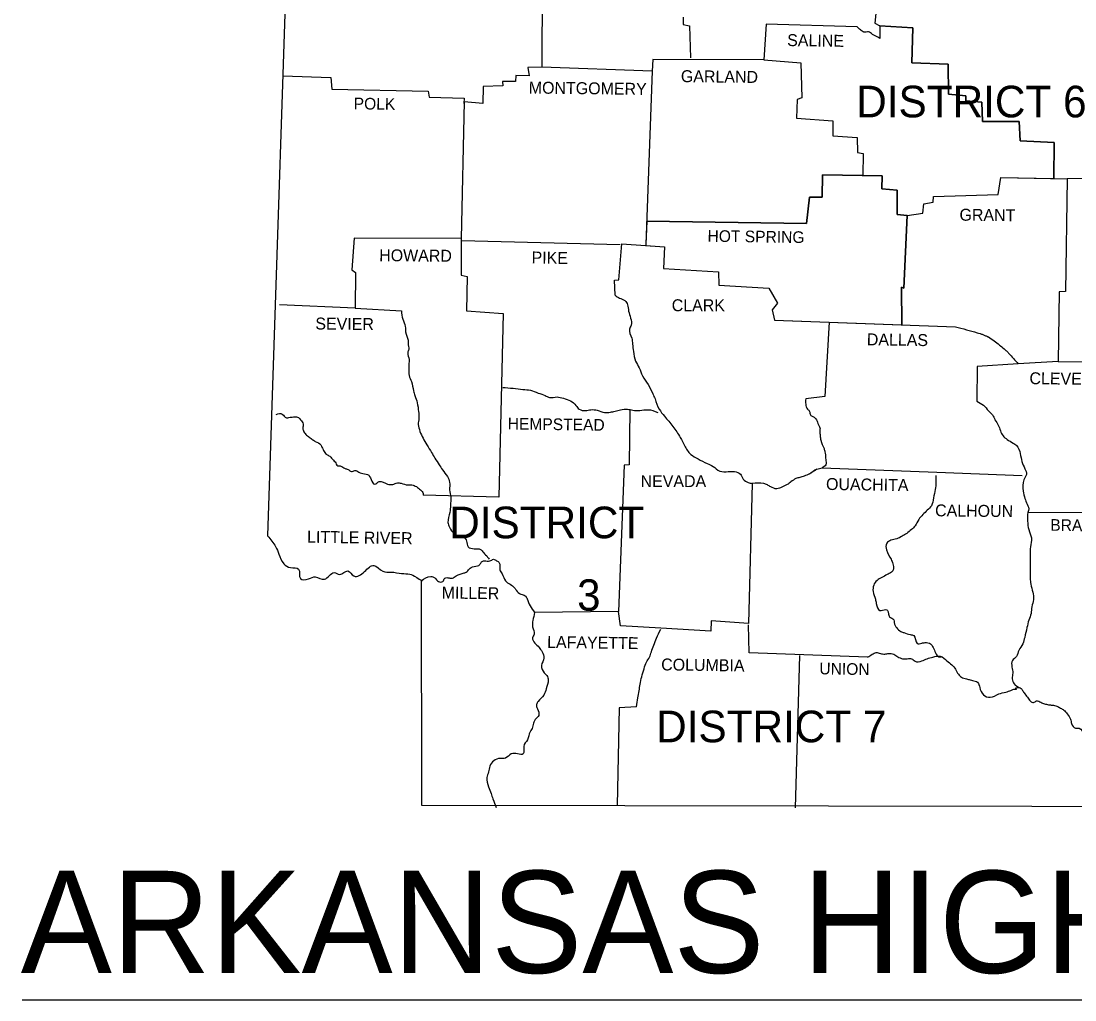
# Model space of a CAD drawing. Extents: x -984 to 3998, y 83 to 2143.
# Drawn here: x 2628.2 to 2999.8, y 1332.5 to 1677.5 of the extents above; entities that cross this region are included whole.
import ezdxf

# ---------------------------------------------------------------- set-up
doc = ezdxf.new("R2010")
doc.units = 0
for name, color, linetype in [('Level 1', 7, 'Continuous'), ('Level 2', 7, 'Continuous'), ('Level 3', 7, 'Continuous'), ('Level 45', 7, 'Continuous')]:
    doc.layers.add(name, color=color, linetype=linetype)

msp = doc.modelspace()

# ---------------------------------------------------------------- linework, layer by layer
at = {"layer": 'Level 1'}
for points in [[(2703.71, 1924.06), (2723.96, 1761.45), (2715.15, 1496.01)], [(2812.02, 1718.5), (2811.82, 1661.26), (2806.93, 1661.16), (2807.32, 1658.23), (2802.62, 1658.32), (2802.53, 1656.17), (2797.93, 1656.17), (2798.03, 1654.61), (2791.18, 1654.41), (2791.08, 1648.44), (2784.43, 1649.03), (2783.35, 1600.89), (2745.68, 1600.99), (2744.8, 1589.84), (2746.17, 1588.86), (2746.07, 1576.33), (2719.36, 1577.51)], [(2961.91, 1690.42), (2954.86, 1691.2), (2955.16, 1688.56), (2942.34, 1688.07), (2941.95, 1684.25), (2929.91, 1683.57), (2929.23, 1676.72), (2930.99, 1675.84), (2930.99, 1671.34)], [(2922.97, 1675.45), (2890.97, 1676.42), (2890.09, 1663.8), (2850.96, 1664), (2850.76, 1659.79)], [(2861.72, 1678.87), (2861.62, 1676.23), (2863.87, 1675.84), (2864.26, 1664.49)], [(2930.99, 1675.78), (2942.63, 1675.05), (2942.24, 1662.82), (2955.06, 1662.34), (2955.26, 1651.67), (2961.32, 1651.18), (2961.32, 1649.32), (2967, 1648.93), (2967.19, 1642.08), (2980.11, 1642.08), (2980.5, 1635.33), (2992.44, 1634.74), (2992.34, 1622.01)], [(2850.76, 1659.79), (2811.82, 1661.26)], [(2890.09, 1663.8), (2903.11, 1662.73), (2903.5, 1650.4), (2901.83, 1649.81), (2901.64, 1643.26), (2914.46, 1642.38), (2914.46, 1636.99), (2922.97, 1636.51), (2923.07, 1631.12), (2925.12, 1630.83), (2925.02, 1623.1)], [(2720.54, 1658.23), (2737.46, 1657.64), (2737.85, 1653.53), (2771.71, 1652.84), (2772.1, 1650.69), (2784.43, 1650.3), (2784.33, 1648.44)], [(2850.76, 1659.79), (2848.51, 1598.84)], [(3109.06, 1633.28), (3072.08, 1634.26), (3071.88, 1622.22), (2997.03, 1621.93)], [(2848.81, 1606.96), (2905.16, 1606.17), (2906.24, 1615.47), (2910.64, 1615.47), (2910.74, 1623.3), (2931.87, 1623), (2931.68, 1618.31), (2937.16, 1617.92), (2937.16, 1609.31), (2940.68, 1609.01)], [(2940.68, 1609.01), (2946.16, 1609.79), (2946.55, 1613.12), (2949.78, 1613.71), (2949.97, 1615.67), (2972.77, 1616.35), (2973.65, 1622.32), (2997.03, 1621.93)], [(2997.04, 1621.93), (2996.45, 1582.2), (2994.2, 1582.11), (2993.9, 1557.55)], [(2940.68, 1609.01), (2939.5, 1583.38), (2938.62, 1583.67), (2938.72, 1570.48)], [(2783.35, 1600.89), (2783.35, 1587.88), (2785.5, 1587.49), (2785.31, 1575.35), (2798.22, 1574.38), (2796.66, 1509.7), (2770.04, 1510.39)], [(2783.55, 1600.21), (2839.51, 1598.74)], [(2837.65, 1580.83), (2837.46, 1586.22), (2839.02, 1586.31), (2840, 1598.93), (2855.07, 1597.96), (2854.68, 1590.23), (2874.15, 1589.15), (2874.24, 1584.45), (2891.85, 1583.38), (2894.89, 1578.09), (2893.03, 1575.75), (2893.91, 1572.13), (2957.7, 1569.78)], [(2746.07, 1576.33), (2762.31, 1575.35)], [(2913.15, 1571.42), (2911.62, 1545.12), (2904.87, 1544.34)], [(2993.9, 1557.55), (2979.78, 1556.68)], [(2993.9, 1557.55), (3028.54, 1557.35)], [(2979.78, 1556.68), (2965.33, 1555.79), (2965.24, 1543.56)], [(2842.84, 1540.62), (2842.64, 1521.15), (2840.88, 1520.96), (2838.92, 1469.39)], [(2910.64, 1519.98), (2951.15, 1518.51), (2981.18, 1517.34)], [(2885.98, 1514.5), (2884.71, 1465.19), (2871.5, 1466.07), (2871.41, 1462.45), (2853.79, 1463.52)], [(2983.14, 1504.32), (3027.36, 1504.42)], [(2769.26, 1480.25), (2769.46, 1401.1), (3128.04, 1400.51)], [(2853.79, 1463.52), (2839.61, 1464.31), (2838.92, 1469.39), (2809.28, 1469.1)], [(2926.69, 1453.25), (2884.91, 1454.82), (2884.71, 1464.7)], [(2902.72, 1453.93), (2901.15, 1400.22)], [(2845.18, 1435.83), (2839.12, 1435.44), (2838.43, 1401)]]:
    msp.add_lwpolyline(points, dxfattribs=at)
for points in [[(2930.99, 1671.34), (2930.31, 1671.83), (2928.45, 1672.8), (2926.98, 1673.68), (2925.41, 1673.59), (2924.14, 1674.37), (2922.97, 1675.45)], [(2837.65, 1580.83), (2839.22, 1579.86), (2841.08, 1578.98), (2842.05, 1577.51), (2842.45, 1575.26), (2843.13, 1572.81), (2843.33, 1570.27), (2842.74, 1568.9), (2843.52, 1565.77), (2843.82, 1563.61), (2844.11, 1561.07), (2844.89, 1557.65), (2846.16, 1555.3), (2847.34, 1552.46), (2849.29, 1549.43), (2850.96, 1546.1), (2851.74, 1544.34), (2853.21, 1540.72), (2855.07, 1538.27), (2858, 1534.56), (2860.64, 1530.74), (2862.11, 1527.9), (2864.36, 1524.77), (2866.91, 1523.21), (2870.13, 1521.54), (2872.19, 1520.56), (2874.54, 1518.9), (2877.57, 1518.71), (2879.82, 1518.71), (2881.88, 1517.82), (2882.85, 1516.06), (2884.61, 1514.89), (2885.98, 1514.5)], [(2762.31, 1575.35), (2762.8, 1572.42), (2763.68, 1569.88), (2763.78, 1567.92), (2764.66, 1564.98), (2764.66, 1563.91), (2764.96, 1561.76), (2764.56, 1560.58), (2765.05, 1558.23), (2764.96, 1556.47), (2764.96, 1555), (2765.05, 1552.56), (2765.84, 1550.41), (2766.62, 1547.18), (2767.11, 1545.51), (2767.89, 1542.97), (2768.38, 1539.84), (2768.48, 1537.49), (2768.28, 1535.34), (2768.87, 1532.89), (2769.95, 1530.45), (2771.32, 1528.1), (2772.98, 1525.46), (2774.15, 1523.4), (2775.62, 1521.15), (2776.79, 1519.29), (2778.56, 1516.94), (2779.34, 1514.99), (2779.34, 1512.25), (2779.73, 1509.7), (2779.63, 1506.87), (2779.44, 1504.32), (2778.75, 1500.8), (2779.24, 1499.14), (2781.1, 1496.69), (2782.27, 1496.01), (2784.33, 1495.61), (2785.31, 1494.24), (2785.89, 1492.19), (2787.95, 1491.51), (2790.2, 1491.31), (2791.27, 1490.14), (2792.74, 1488.57), (2793.23, 1487.79)], [(2957.7, 1569.78), (2965.33, 1567.63), (2966.33, 1567.33), (2967.32, 1567), (2968.3, 1566.61), (2968.77, 1566.4), (2969.01, 1566.28), (2969.25, 1566.16), (2971.28, 1564.84), (2973.16, 1563.32), (2974.83, 1561.96), (2975.64, 1561.25), (2976.39, 1560.48), (2979.78, 1556.68)], [(2798.03, 1548.35), (2801.74, 1548.06), (2805.17, 1547.67), (2807.81, 1547.37), (2810.55, 1546.39), (2813, 1545.51), (2814.56, 1544.83), (2817.2, 1545.02), (2819.45, 1544.54), (2822, 1543.65), (2823.86, 1541.99), (2825.03, 1540.72), (2827.28, 1540.23), (2829.14, 1540.52), (2831.39, 1540.33), (2833.93, 1539.55), (2835.99, 1539.64), (2837.65, 1540.03), (2839.61, 1540.52), (2842.05, 1540.72), (2843.91, 1540.33), (2846.36, 1540.23), (2849.2, 1540.52), (2852.72, 1539.55)], [(2904.87, 1544.34), (2904.87, 1542.48), (2905.55, 1540.72), (2906.24, 1539.94), (2906.53, 1538.66), (2907.41, 1538.08), (2908.68, 1536.9), (2909.37, 1535.24), (2909.86, 1534.16), (2909.86, 1532.79), (2909.96, 1531.42), (2910.15, 1529.76), (2911.33, 1526.83), (2911.62, 1525.65), (2911.81, 1524.67), (2911.91, 1523.01), (2911.91, 1521.05), (2910.64, 1519.98)], [(2965.24, 1543.56), (2967.49, 1542.09), (2969.34, 1540.13), (2970.71, 1538.66), (2971.59, 1537), (2972.77, 1535.04), (2974.43, 1531.33), (2975.9, 1530.05), (2977.95, 1528.78), (2979.23, 1527.9), (2980.5, 1525.06), (2981.09, 1522.23), (2982.16, 1519.68), (2982.65, 1517.73), (2981.77, 1515.77), (2981.57, 1511.86), (2982.16, 1509.21), (2982.94, 1507.26), (2983.43, 1505.01), (2983.14, 1504.32)], [(2718.19, 1538.86), (2720.34, 1538.96), (2721.81, 1537.69), (2722.69, 1537.78), (2724.25, 1537.98), (2725.72, 1537.88), (2726.8, 1537), (2727.68, 1535.44), (2727.58, 1533.97), (2727.68, 1533.38), (2728.36, 1532.11), (2729.54, 1531.13), (2730.81, 1530.15), (2731.98, 1529.37), (2733.94, 1528.1), (2734.14, 1527.71), (2734.92, 1526.14), (2735.9, 1524.87), (2737.07, 1524.09), (2738.34, 1522.72), (2738.93, 1522.13), (2739.91, 1520.76), (2740.98, 1520.66), (2742.45, 1519.78), (2743.53, 1519.49), (2744.7, 1518.71), (2745.88, 1519.1), (2747.34, 1518.51), (2749.3, 1517.92), (2750.38, 1517.73), (2751.65, 1515.87), (2752.92, 1514.3), (2754.49, 1515.18), (2757.42, 1514.3), (2759.28, 1514.2), (2760.94, 1514.69), (2762.22, 1514.6), (2764.56, 1514.01), (2766.03, 1514.01), (2767.6, 1513.42), (2769.06, 1512.25), (2770.04, 1510.98), (2770.04, 1510.39)], [(2908.78, 1519.59), (2906.24, 1517.92), (2904.28, 1517.14), (2902.81, 1516.65), (2901.44, 1516.26), (2899.68, 1515.09), (2898.31, 1514.11), (2896.45, 1513.23), (2894.69, 1512.64), (2892.54, 1513.32), (2891.37, 1514.01), (2890.09, 1514.5), (2885.98, 1514.5)], [(2906.24, 1517.92), (2908.78, 1519.59), (2910.64, 1519.98)], [(2950.75, 1517.34), (2950.56, 1512.44), (2949.87, 1509.41), (2949.19, 1506.67), (2947.72, 1505.11), (2946.16, 1503.54), (2944.69, 1501.78), (2943.42, 1499.63), (2942.14, 1498.26), (2940.48, 1496.89), (2938.82, 1495.91), (2936.96, 1495.03), (2934.9, 1494.54), (2933.44, 1493.46), (2933.34, 1491.11), (2935, 1487.79), (2935.59, 1486.22), (2935.79, 1484.36), (2935.1, 1483.29), (2933.53, 1482.41), (2931.68, 1481.33), (2930.01, 1480.35), (2928.84, 1478.69), (2928.64, 1476.44), (2929.43, 1473.8), (2929.72, 1472.23), (2930.99, 1469.78), (2931.97, 1469.88), (2933.73, 1469.78), (2933.93, 1469.3), (2934.02, 1468.81), (2934.42, 1467.53), (2935.88, 1466.46), (2936.08, 1465.48), (2936.96, 1463.62), (2938.43, 1462.35), (2939.5, 1461.96), (2941.75, 1461.27), (2942.93, 1460.98), (2944.2, 1458.14), (2945.77, 1458.24), (2946.94, 1458.44), (2948.9, 1457.95), (2949.78, 1456.77), (2950.66, 1454.82), (2951.83, 1453.45), (2952.61, 1453.45)], [(2983.14, 1504.32), (2983.53, 1498.26), (2984.41, 1495.32), (2984.12, 1492.19), (2984.02, 1489.16), (2984.02, 1486.42), (2984.02, 1483.78), (2984.02, 1481.04), (2984.22, 1479.08), (2984.9, 1476.24), (2985.19, 1473.6), (2984.61, 1471.06), (2984.31, 1468.71), (2983.53, 1466.36), (2982.85, 1463.72), (2982.06, 1460.29), (2981.38, 1458.04), (2980.01, 1455.7), (2979.13, 1453.54), (2977.76, 1452.17), (2977.56, 1449.83), (2977.86, 1447.67), (2977.66, 1445.72), (2978.35, 1443.86), (2980.11, 1442.59)], [(2715.15, 1496.01), (2717.99, 1492.29), (2719.17, 1489.65), (2720.83, 1486.22), (2723.28, 1484.85), (2726.11, 1484.36), (2726.7, 1481.04), (2729.63, 1480.94), (2731.98, 1481.62), (2735.21, 1480.74), (2738.64, 1483.09), (2740.59, 1482.5), (2743.43, 1483.68), (2745.58, 1481.92), (2749.3, 1483.48), (2752.63, 1485.64), (2755.76, 1483.58), (2758.79, 1483.29), (2762.41, 1482.8), (2765.25, 1482.6), (2767.79, 1481.33), (2769.65, 1480.06), (2769.26, 1480.25)], [(2769.26, 1480.25), (2772.68, 1481.72), (2774.15, 1481.23), (2775.42, 1479.96), (2776.89, 1479.96), (2777.67, 1481.13), (2779.14, 1481.23), (2780.32, 1481.13), (2781.59, 1481.92), (2782.66, 1482.41), (2784.13, 1482.9), (2785.21, 1483.29), (2786.19, 1484.36), (2787.95, 1485.24), (2790, 1485.93), (2790.59, 1486.91), (2791.57, 1487.3), (2793.52, 1487.2), (2794.8, 1487.79), (2795.87, 1487.3), (2796.85, 1486.61), (2797.05, 1484.07), (2797.83, 1482.7), (2799, 1480.25), (2800.67, 1478.98), (2802.23, 1477.71), (2802.82, 1476.93), (2804.48, 1475.46), (2805.95, 1474.97), (2806.64, 1473.89), (2807.71, 1471.35), (2809.28, 1469.1)], [(2809.28, 1469.1), (2808.69, 1466.26), (2808.59, 1464.01), (2809.08, 1461.37), (2808.59, 1460.1), (2809.38, 1458.24), (2810.84, 1456.77), (2811.92, 1455.21), (2812.6, 1452.96), (2811.72, 1450.41), (2812.7, 1447.77), (2813.58, 1446.79), (2814.07, 1445.23), (2813.39, 1442.19), (2812.51, 1439.94), (2810.55, 1437.69), (2809.96, 1436.62), (2810.26, 1435.15), (2810.74, 1432.8), (2810.26, 1432.12), (2808.98, 1430.45), (2808.59, 1428.59), (2807.71, 1427.03), (2806.73, 1424.19), (2805.46, 1421.84), (2805.27, 1419.2), (2803.31, 1419.2), (2801.06, 1419.2), (2799, 1417.73), (2797.15, 1417.64), (2794.89, 1416.76), (2793.52, 1414.9), (2793.04, 1412.84), (2792.45, 1410.88), (2793.04, 1407.56), (2793.92, 1405.21), (2794.6, 1403.35), (2795.78, 1400.32)], [(2845.18, 1435.83), (2845.67, 1438.97), (2846.16, 1441.41), (2846.46, 1443.76), (2847.04, 1446.4), (2847.92, 1449.24), (2848.71, 1451.59), (2849.78, 1453.25), (2850.47, 1455.21), (2851.35, 1457.55), (2852.23, 1460), (2853.79, 1463.13)], [(2926.69, 1453.25), (2928.25, 1454.33), (2929.72, 1454.91), (2931.19, 1454.62), (2932.75, 1454.42), (2934.12, 1454.62), (2935.88, 1454.33), (2937.35, 1453.45), (2939.01, 1452.76), (2940.68, 1452.76), (2942.14, 1452.76), (2943.42, 1451.88), (2945.77, 1451.98), (2947.72, 1452.76), (2949.68, 1453.35), (2952.32, 1453.64), (2954.67, 1451.98), (2956.33, 1450.61), (2957.7, 1449.04), (2958.68, 1447.28), (2959.76, 1446.3), (2961.52, 1445.62), (2962.89, 1445.32), (2964.55, 1444.84), (2965.43, 1444.44), (2966.21, 1442.59), (2967.49, 1440.04), (2969.93, 1439.16), (2972.96, 1440.33), (2975.41, 1441.02), (2977.17, 1441.61), (2978.25, 1442), (2979.23, 1442.1), (2978.93, 1442.29), (2980.11, 1442.59), (2981.18, 1441.8), (2981.87, 1440.73), (2983.04, 1439.16), (2984.12, 1437.79), (2985.19, 1437.3), (2986.27, 1437.89), (2987.74, 1437.4), (2989.01, 1436.91), (2990.48, 1436.52), (2991.75, 1436.42), (2993.41, 1436.03), (2994.69, 1435.34), (2995.86, 1434.66), (2997.03, 1433.39), (2998.21, 1431.43), (2998.6, 1429.87), (2999.97, 1428.3), (3001.24, 1428.3), (3003.1, 1425.76), (3003.78, 1424.78), (3005.25, 1423.02), (3006.33, 1423.02), (3008.38, 1422.63)]]:
    msp.add_spline(points, degree=3, dxfattribs=at)
at = {"layer": 'Level 2'}
msp.add_line((2628.58, 1332.51), (3283.1, 1332.51), dxfattribs=at)
at = {"layer": 'Level 45'}
for p, q in [((2930.99, 1675.78), (2930.99, 1671.34)), ((2931.68, 1618.31), (2931.87, 1623)), ((2937.16, 1617.92), (2931.68, 1618.31)), ((2848.81, 1606.96), (2848.51, 1598.84)), ((2848.51, 1598.84), (2848.48, 1598.38))]:
    msp.add_line(p, q, dxfattribs=at)
for points in [[(2922.97, 1675.45), (2890.97, 1676.42), (2890.09, 1663.8)], [(2992.34, 1622.01), (2992.44, 1634.74), (2980.5, 1635.33), (2980.11, 1642.08), (2967.19, 1642.08), (2967, 1648.93), (2961.32, 1649.32), (2961.32, 1651.18), (2955.26, 1651.67), (2955.06, 1662.34), (2942.24, 1662.82), (2942.63, 1675.05), (2930.99, 1675.78)], [(2890.09, 1663.8), (2903.11, 1662.73), (2903.5, 1650.4), (2901.83, 1649.81), (2901.64, 1643.26), (2914.46, 1642.38), (2914.46, 1636.99), (2922.97, 1636.51), (2923.07, 1631.12), (2925.12, 1630.83), (2925.02, 1623.1)], [(2931.87, 1623), (2925.02, 1623.1), (2910.74, 1623.3), (2910.64, 1615.47), (2906.24, 1615.47), (2905.16, 1606.17), (2848.81, 1606.96)], [(2925.02, 1623.1), (2931.87, 1623), (2931.68, 1618.31), (2937.16, 1617.92), (2937.16, 1609.31), (2940.68, 1609.01)], [(2940.68, 1609.01), (2946.16, 1609.79), (2946.55, 1613.12), (2949.78, 1613.71), (2949.97, 1615.67), (2972.77, 1616.35), (2973.65, 1622.32), (2992.34, 1622.01)], [(2940.68, 1609.01), (2937.16, 1609.31), (2937.16, 1617.92)], [(2938.72, 1570.48), (2938.62, 1583.67), (2939.5, 1583.38), (2940.68, 1609.01)], [(2848.48, 1598.38), (2855.07, 1597.96), (2854.68, 1590.23), (2874.15, 1589.15), (2874.24, 1584.45), (2891.85, 1583.38), (2894.89, 1578.09), (2893.03, 1575.75), (2893.91, 1572.13), (2938.72, 1570.48)]]:
    msp.add_lwpolyline(points, dxfattribs=at)
msp.add_spline([(2930.99, 1671.34), (2930.31, 1671.83), (2928.45, 1672.8), (2926.98, 1673.68), (2925.41, 1673.59), (2924.14, 1674.37), (2922.97, 1675.45)], degree=3, dxfattribs=at)

# ---------------------------------------------------------------- texts
at = {"layer": 'Level 2'}
for s, height, rotation, p in [('SALINE', 4.21, 359.1491, (2898.31, 1668.69)), ('GARLAND', 4.207, 359.3658, (2860.84, 1655.98)), ('MONTGOMERY', 4.207, 359.2944, (2807.22, 1651.96)), ('POLK', 4.108, 359.2152, (2745.49, 1646.39)), ('GRANT', 4.207, 359.4032, (2959.07, 1607.15)), ('HOT SPRING', 4.109, 359.2216, (2870.23, 1599.72)), ('HOWARD', 4.207, 359.5145, (2754.49, 1592.87)), ('PIKE', 4.206, 359.0452, (2808.2, 1592.09)), ('SEVIER', 4.207, 359.4271, (2731.98, 1568.8)), ('DALLAS', 4.206, 359.2462, (2926.39, 1563.22)), ('CLEVELAND', 4.207, 359.3377, (2983.73, 1549.52)), ('HEMPSTEAD', 4.108, 359.1885, (2799.79, 1533.58)), ('OUACHITA', 4.207, 359.2043, (2912.01, 1512.25)), ('CALHOUN', 4.207, 359.3634, (2950.46, 1502.95)), ('BRADLEY', 4.108, 359.1449, (2991.07, 1497.87)), ('LITTLE RIVER', 4.2073, 359.1697, (2729.05, 1493.66)), ('MILLER', 4.206, 359.1319, (2776.5, 1473.99)), ('LAFAYETTE', 4.206, 359.1839, (2813.68, 1456.58)), ('COLUMBIA', 4.206, 359.2125, (2853.89, 1448.65)), ('UNION', 4.109, 358.9584, (2909.66, 1447.28))]:
    msp.add_text(s, height=height, rotation=rotation, dxfattribs=at).set_placement(p)
for s, height, p in [('CLARK', 4.207, (2857.63, 1575.23)), ('NEVADA', 4.207, (2846.65, 1513.23)), ('ARKANSAS HIGHWAY DISTRICT 6', 36, (2628.15, 1342.01))]:
    msp.add_text(s, height=height, dxfattribs=at).set_placement(p)
at = {"layer": 'Level 3'}
for s, height, p in [('DISTRICT 6', 11.154, (2922.67, 1643.55)), ('DISTRICT', 11.154, (2779.19, 1495.21)), ('3', 11.06, (2824.3, 1469.68)), ('DISTRICT 7', 11.154, (2852.13, 1423.31))]:
    msp.add_text(s, height=height, dxfattribs=at).set_placement(p)

doc.saveas('drawing.dxf')
